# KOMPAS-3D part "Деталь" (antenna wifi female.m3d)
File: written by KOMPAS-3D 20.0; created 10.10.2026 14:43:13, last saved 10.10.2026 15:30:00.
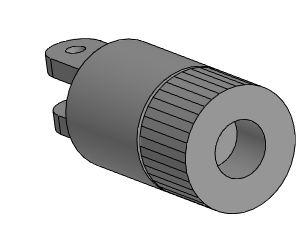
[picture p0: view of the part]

Document properties: Полное имя файла: D:\myProjects\Progect_esp32\box_compas\wifi\antenna wifi female.m3d

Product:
- Part/product: Деталь
    Масса: 0.022341

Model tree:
1. Эскиз:1
2. Элемент выдавливания:1
     Расстояние 1 = 8
3. Эскиз:2  (with: Элемент выдавливания:1)
4. Элемент выдавливания:2
     Расстояние 1 = 0.5
5. Эскиз:3  (with: Элемент выдавливания:2)
6. Элемент выдавливания:3
     Расстояние 1 = 12.5
7. Эскиз:4  (with: Элемент выдавливания:1)
8. Элемент выдавливания:4
     Расстояние 2 = 8
9. Эскиз:5  (with: Элемент выдавливания:1)
10. Элемент выдавливания:5
     Расстояние 2 = 5
11. Эскиз:6  (with: Элемент выдавливания:3)
12. Элемент выдавливания:7
     Расстояние 1 = 10
13. Скругление:1  (with: Элемент выдавливания:7)
     Радиус = 3
14. Эскиз:7  (with: Элемент выдавливания:7)
15. Элемент выдавливания:8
